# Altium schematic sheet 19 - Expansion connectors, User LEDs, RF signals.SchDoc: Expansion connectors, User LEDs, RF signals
size A3; PageSetup: Record=PageOptions¦CenterHorizontal=True¦CenterVertical=True¦PrintScale=0.70¦XCorrection=1.00¦YCorrection=1.00¦PrintKind=0¦BorderSize=5000000¦LeftOffset=0¦BottomOffset=0¦Orientation=2¦PaperLength=4200¦PaperWidth=2970¦Scale=100¦PaperSource=7¦PrintQuality=600¦MediaType=1¦DitherType=10¦PaperKind=A4¦PrintScaleMode=1; Author: Juan Anzola; SheetNumber: 19; SheetTotal: 21
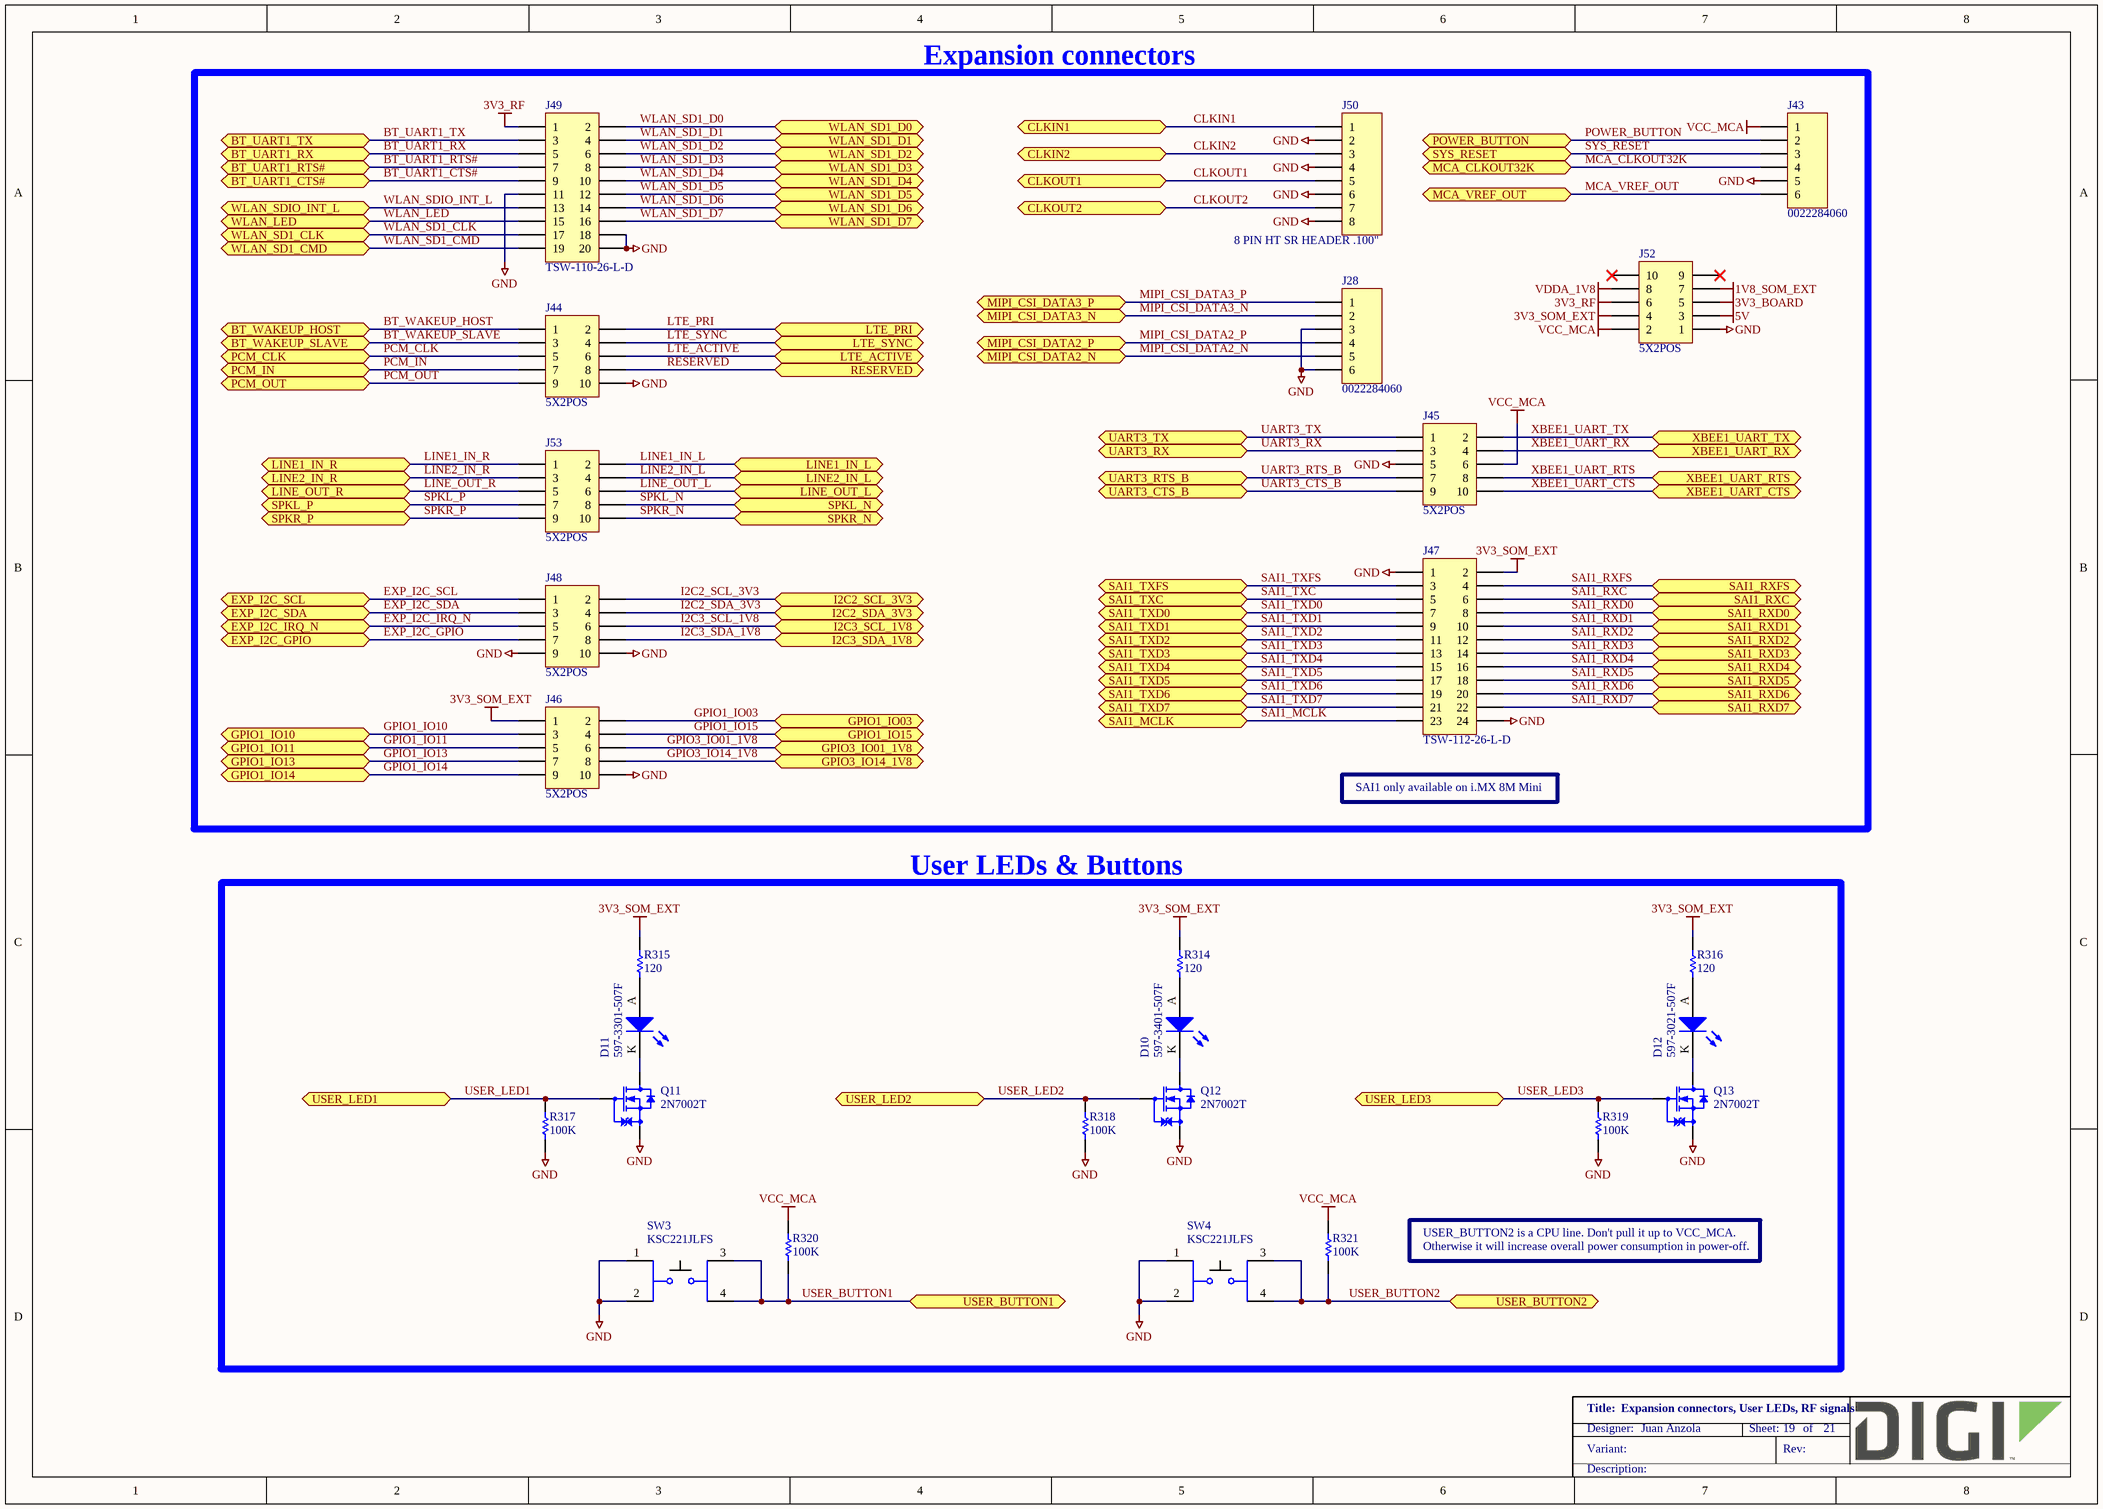
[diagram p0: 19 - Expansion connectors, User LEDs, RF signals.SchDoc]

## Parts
D10  597-3401-507F  [LEDM3020X130N_YELLOW]
D11  597-3301-507F  [LEDM3020X130N_GREEN]
D12  597-3021-507F  [LEDM3020X130N]
J28  0022284060  [MOLEX_0022284060]
J43  0022284060  [MOLEX_0022284060]
J44  5X2POS  [MOLEX_87914-1016]
J45  5X2POS  [MOLEX_87914-1016]
J46  5X2POS  [MOLEX_87914-1016]
J47  TSW-112-26-L-D  [SAMTEC_TSW-112-26-L-D]
J48  5X2POS  [MOLEX_87914-1016]
J49  TSW-110-26-L-D  [SAMTEC_TSW-110-26-L-D]
J50  8 PIN HT SR HEADER .100"  [SAMTEC_TSW-108-07-X-S]
J52  5X2POS  [MOLEX_87914-1016]
J53  5X2POS  [MOLEX_87914-1016]
Q11  2N7002T  [SOTFL50P160X80_GSD-3N]
Q12  2N7002T  [SOTFL50P160X80_GSD-3N]
Q13  2N7002T  [SOTFL50P160X80_GSD-3N]
R314  120  [RESC1005X40N]
R315  120  [RESC1005X40N]
R316  120  [RESC1005X40N]
R317  100K  [RESC1005X40N]
R318  100K  [RESC1005X40N]
R319  100K  [RESC1005X40N]
R320  100K  [RESC1005X40N]
R321  100K  [RESC1005X40N]
SW3  KSC221JLFS  [SW_KSC221J]
SW4  KSC221JLFS  [SW_KSC221J]

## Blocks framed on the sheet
Expansion connectors: J28 J43-J50 J52 J53
User LEDs & Buttons: D10-D12 Q11-Q13 R314-R321 SW3 SW4

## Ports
BT_UART1_CTS# (bidir), BT_UART1_RTS# (bidir), BT_UART1_RX (bidir), BT_UART1_TX (bidir), BT_WAKEUP_HOST (bidir), BT_WAKEUP_SLAVE (bidir), CLKIN1 (bidir), CLKIN2 (bidir), CLKOUT1 (bidir), CLKOUT2 (bidir), EXP_I2C_GPIO (bidir), EXP_I2C_IRQ_N (bidir), EXP_I2C_SCL (bidir), EXP_I2C_SDA (bidir), GPIO1_IO03 (bidir), GPIO1_IO10 (bidir), GPIO1_IO11 (bidir), GPIO1_IO13 (bidir), GPIO1_IO14 (bidir), GPIO1_IO15 (bidir), GPIO3_IO01_1V8 (bidir), GPIO3_IO14_1V8 (bidir), I2C2_SCL_3V3 (bidir), I2C2_SDA_3V3 (bidir), I2C3_SCL_1V8 (bidir), I2C3_SDA_1V8 (bidir), LINE1_IN_L (bidir), LINE1_IN_R (bidir), LINE2_IN_L (bidir), LINE2_IN_R (bidir), LINE_OUT_L (bidir), LINE_OUT_R (bidir), LTE_ACTIVE (bidir), LTE_PRI (bidir), LTE_SYNC (bidir), MCA_CLKOUT32K (bidir), MCA_VREF_OUT (bidir), MIPI_CSI_DATA2_N (bidir), MIPI_CSI_DATA2_P (bidir), MIPI_CSI_DATA3_N (bidir), MIPI_CSI_DATA3_P (bidir), PCM_CLK (bidir), PCM_IN (bidir), PCM_OUT (bidir), POWER_BUTTON (bidir), RESERVED (bidir), SAI1_MCLK (bidir), SAI1_RXC (bidir), SAI1_RXD0 (bidir), SAI1_RXD1 (bidir), SAI1_RXD2 (bidir), SAI1_RXD3 (bidir), SAI1_RXD4 (bidir), SAI1_RXD5 (bidir), SAI1_RXD6 (bidir), SAI1_RXD7 (bidir), SAI1_RXFS (bidir), SAI1_TXC (bidir), SAI1_TXD0 (bidir), SAI1_TXD1 (bidir), SAI1_TXD2 (bidir), SAI1_TXD3 (bidir), SAI1_TXD4 (bidir), SAI1_TXD5 (bidir), SAI1_TXD6 (bidir), SAI1_TXD7 (bidir), SAI1_TXFS (bidir), SPKL_N (bidir), SPKL_P (bidir), SPKR_N (bidir), SPKR_P (bidir), SYS_RESET (bidir), UART3_CTS_B (bidir), UART3_RTS_B (bidir), UART3_RX (bidir), UART3_TX (bidir), USER_BUTTON1 (bidir), USER_BUTTON2 (bidir), USER_LED1 (bidir), USER_LED2 (bidir), USER_LED3 (bidir), WLAN_LED (bidir), WLAN_SD1_CLK (bidir), WLAN_SD1_CMD (bidir), WLAN_SD1_D0 (bidir), WLAN_SD1_D1 (bidir), WLAN_SD1_D2 (bidir), WLAN_SD1_D3 (bidir), WLAN_SD1_D4 (bidir), WLAN_SD1_D5 (bidir), WLAN_SD1_D6 (bidir), WLAN_SD1_D7 (bidir), WLAN_SDIO_INT_L (bidir), XBEE1_UART_CTS (bidir), XBEE1_UART_RTS (bidir), XBEE1_UART_RX (bidir), XBEE1_UART_TX (bidir)

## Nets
1V8_SOM_EXT: J52.7
3V3_BOARD: J52.5
3V3_RF: J49.1 J52.6
3V3_SOM_EXT: J46.1 J47.2 J52.4 R314.2 R315.2 R316.2
5V: J52.3
GND: J28.3 J28.6 J43.5 J44.10 J45.5 J46.10 J47.1 J47.24 J48.9 J48.10 J49.11 J49.18 J49.20 J50.2 J50.4 J50.6 J50.8 J52.1 Q11.S Q12.S Q13.S R317.2 R318.2 R319.2 SW3.1 SW3.2 SW4.1 SW4.2
VCC_MCA: J43.1 J45.6 J52.2 R320.2 R321.2
VDDA_1V8: J52.8
BT_UART1_CTS#: J49.9 ; port BT_UART1_CTS#
BT_UART1_RTS#: J49.7 ; port BT_UART1_RTS#
BT_UART1_RX: J49.5 ; port BT_UART1_RX
BT_UART1_TX: J49.3 ; port BT_UART1_TX
BT_WAKEUP_HOST: J44.1 ; port BT_WAKEUP_HOST
BT_WAKEUP_SLAVE: J44.3 ; port BT_WAKEUP_SLAVE
CLKIN1: J50.1 ; port CLKIN1
CLKIN2: J50.3 ; port CLKIN2
CLKOUT1: J50.5 ; port CLKOUT1
CLKOUT2: J50.7 ; port CLKOUT2
EXP_I2C_GPIO: J48.7 ; port EXP_I2C_GPIO
EXP_I2C_IRQ_N: J48.5 ; port EXP_I2C_IRQ_N
EXP_I2C_SCL: J48.1 ; port EXP_I2C_SCL
EXP_I2C_SDA: J48.3 ; port EXP_I2C_SDA
GPIO1_IO03: J46.2 ; port GPIO1_IO03
GPIO1_IO10: J46.3 ; port GPIO1_IO10
GPIO1_IO11: J46.5 ; port GPIO1_IO11
GPIO1_IO13: J46.7 ; port GPIO1_IO13
GPIO1_IO14: J46.9 ; port GPIO1_IO14
GPIO1_IO15: J46.4 ; port GPIO1_IO15
GPIO3_IO01_1V8: J46.6 ; port GPIO3_IO01_1V8
GPIO3_IO14_1V8: J46.8 ; port GPIO3_IO14_1V8
I2C2_SCL_3V3: J48.2 ; port I2C2_SCL_3V3
I2C2_SDA_3V3: J48.4 ; port I2C2_SDA_3V3
I2C3_SCL_1V8: J48.6 ; port I2C3_SCL_1V8
I2C3_SDA_1V8: J48.8 ; port I2C3_SDA_1V8
LINE1_IN_L: J53.2 ; port LINE1_IN_L
LINE1_IN_R: J53.1 ; port LINE1_IN_R
LINE2_IN_L: J53.4 ; port LINE2_IN_L
LINE2_IN_R: J53.3 ; port LINE2_IN_R
LINE_OUT_L: J53.6 ; port LINE_OUT_L
LINE_OUT_R: J53.5 ; port LINE_OUT_R
LTE_ACTIVE: J44.6 ; port LTE_ACTIVE
LTE_PRI: J44.2 ; port LTE_PRI
LTE_SYNC: J44.4 ; port LTE_SYNC
MCA_CLKOUT32K: J43.4 ; port MCA_CLKOUT32K
MCA_VREF_OUT: J43.6 ; port MCA_VREF_OUT
MIPI_CSI_DATA2_N: J28.5 ; port MIPI_CSI_DATA2_N
MIPI_CSI_DATA2_P: J28.4 ; port MIPI_CSI_DATA2_P
MIPI_CSI_DATA3_N: J28.2 ; port MIPI_CSI_DATA3_N
MIPI_CSI_DATA3_P: J28.1 ; port MIPI_CSI_DATA3_P
PCM_CLK: J44.5 ; port PCM_CLK
PCM_IN: J44.7 ; port PCM_IN
PCM_OUT: J44.9 ; port PCM_OUT
POWER_BUTTON: J43.2 ; port POWER_BUTTON
RESERVED: J44.8 ; port RESERVED
SAI1_MCLK: J47.23 ; port SAI1_MCLK
SAI1_RXC: J47.6 ; port SAI1_RXC
SAI1_RXD0: J47.8 ; port SAI1_RXD0
SAI1_RXD1: J47.10 ; port SAI1_RXD1
SAI1_RXD2: J47.12 ; port SAI1_RXD2
SAI1_RXD3: J47.14 ; port SAI1_RXD3
SAI1_RXD4: J47.16 ; port SAI1_RXD4
SAI1_RXD5: J47.18 ; port SAI1_RXD5
SAI1_RXD6: J47.20 ; port SAI1_RXD6
SAI1_RXD7: J47.22 ; port SAI1_RXD7
SAI1_RXFS: J47.4 ; port SAI1_RXFS
SAI1_TXC: J47.5 ; port SAI1_TXC
SAI1_TXD0: J47.7 ; port SAI1_TXD0
SAI1_TXD1: J47.9 ; port SAI1_TXD1
SAI1_TXD2: J47.11 ; port SAI1_TXD2
SAI1_TXD3: J47.13 ; port SAI1_TXD3
SAI1_TXD4: J47.15 ; port SAI1_TXD4
SAI1_TXD5: J47.17 ; port SAI1_TXD5
SAI1_TXD6: J47.19 ; port SAI1_TXD6
SAI1_TXD7: J47.21 ; port SAI1_TXD7
SAI1_TXFS: J47.3 ; port SAI1_TXFS
SPKL_N: J53.8 ; port SPKL_N
SPKL_P: J53.7 ; port SPKL_P
SPKR_N: J53.10 ; port SPKR_N
SPKR_P: J53.9 ; port SPKR_P
SYS_RESET: J43.3 ; port SYS_RESET
UART3_CTS_B: J45.9 ; port UART3_CTS_B
UART3_RTS_B: J45.7 ; port UART3_RTS_B
UART3_RX: J45.3 ; port UART3_RX
UART3_TX: J45.1 ; port UART3_TX
USER_BUTTON1: R320.1 SW3.3 SW3.4 ; port USER_BUTTON1
USER_BUTTON2: R321.1 SW4.3 SW4.4 ; port USER_BUTTON2
USER_LED1: Q11.G R317.1 ; port USER_LED1
USER_LED2: Q12.G R318.1 ; port USER_LED2
USER_LED3: Q13.G R319.1 ; port USER_LED3
WLAN_LED: J49.15 ; port WLAN_LED
WLAN_SD1_CLK: J49.17 ; port WLAN_SD1_CLK
WLAN_SD1_CMD: J49.19 ; port WLAN_SD1_CMD
WLAN_SD1_D0: J49.2 ; port WLAN_SD1_D0
WLAN_SD1_D1: J49.4 ; port WLAN_SD1_D1
WLAN_SD1_D2: J49.6 ; port WLAN_SD1_D2
WLAN_SD1_D3: J49.8 ; port WLAN_SD1_D3
WLAN_SD1_D4: J49.10 ; port WLAN_SD1_D4
WLAN_SD1_D5: J49.12 ; port WLAN_SD1_D5
WLAN_SD1_D6: J49.14 ; port WLAN_SD1_D6
WLAN_SD1_D7: J49.16 ; port WLAN_SD1_D7
WLAN_SDIO_INT_L: J49.13 ; port WLAN_SDIO_INT_L
XBEE1_UART_CTS: J45.10 ; port XBEE1_UART_CTS
XBEE1_UART_RTS: J45.8 ; port XBEE1_UART_RTS
XBEE1_UART_RX: J45.4 ; port XBEE1_UART_RX
XBEE1_UART_TX: J45.2 ; port XBEE1_UART_TX
NetD10_A: D10.A R314.1
NetD10_K: D10.K Q12.D
NetD11_A: D11.A R315.1
NetD11_K: D11.K Q11.D
NetD12_A: D12.A R316.1
NetD12_K: D12.K Q13.D

Not connected (* = marked no-connect by the designer): J52 9* 10*

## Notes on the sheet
- SAI1 only available on i.MX 8M Mini
- USER_BUTTON2 is a CPU line. Don't pull it up to VCC_MCA.
- Otherwise it will increase overall power consumption in power-off.

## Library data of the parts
D10 = 1001188: LED YELLOW 588NM 1208 SMD; Manufacturer: Dialight; Note: 17050842 = Digi No. for GE WDNU; Digi_PN: 17050387; Component_Life_Cycle_State: Reviewed; Area: 6
D11 = 1001189: LED GREEN 573NM 1208 SMD; Manufacturer: Dialight; Note: 17050846 = Digi PN for GE WDNU II; Digi_PN: 17050183; Component_Life_Cycle_State: Reviewed; Area: 6
D12 = 1001190: LED RED 653NM 20MA 1208 SMD; Manufacturer: Dialight; Digi_PN: 17050184; Component_Life_Cycle_State: Reviewed; Area: 6
J28 J43 = 1002721: CONN HEADER VERT 6POS 2.54MM; Part_Type: Connector; Manufacturer: Molex; Digi_PN: 0790004; Component_Life_Cycle_State: Reviewed; Area: 42,49
J44-J46 J48 J52 J53 = 1001335: CONN HEADER 10POS DL VERT T/H; Part_Type: Connector; Manufacturer: Molex; Manufacturer_Part_Number: 87914-1016; Note: Check symbol pin-out upon reactivation; Digi_PN: 18000793; Component_Life_Cycle_State: Abandoned; Area: 63,5
J47 = 1002752: CONN HEADER VERT 24POS 2.54MM; Part_Type: Connector; Manufacturer: Samtec; Digi_PN: 18000795; Component_Life_Cycle_State: Created; Area: 179,25
J49 = 1002751: CONN HEADER VERT 20POS 2.54MM; Part_Type: Connector; Manufacturer: Samtec; Digi_PN: 01730020; Component_Life_Cycle_State: Created; Area: 150,08
J50 = 1000191: CONN HEADER 8POS .100" SNGL; Part_Type: Connector; Manufacturer: Samtec; Manufacturer_Part_Number: TSW-108-07-G-S; Component_Life_Cycle_State: Reviewed; Area: 51,61; Digi_PN: 18000792
Q11-Q13 = 1000715: MOSFET N-CH 60V 115MA SOT-523F; Part_Type: Transistor; Manufacturer: Fairchild Semiconductor; Digi_PN: 17050797; Component_Life_Cycle_State: CAD Reviewed; Area: 3.06; Project: SmartMeter2; Note: 17050841 = Digi No. for GE WDNU
R314-R316 = 1001158: RES 120 OHM 1/16W 1% 0402 SMD; Part_Type: Resistor; Manufacturer: Yageo; Manufacturer_Part_Number: RC0402FR-07120RL; Note: 13051102 = Digi No. for GE WDNU; Digi_PN: 13050832; Component_Life_Cycle_State: Reviewed; Area: 0,95; Project: CCWMX6_SBC board
R317-R319 = 1000480: RES 100K OHM 1/10W 1% 0402 SMD; Part_Type: Resistor; Manufacturer: Panasonic - ECG; Manufacturer_Part_Number: ERJ-2RKF1003X; Digi_PN: 13051063; Component_Life_Cycle_State: CAD Reviewed; Area: 0.95; Project: KITT; Power_WV_SRF: 100
R320 R321 = 1000480: RES 100K OHM 1/10W 1% 0402 SMD; Part_Type: Resistor; Manufacturer: Panasonic - ECG; Manufacturer_Part_Number: ERJ-2RKF1003X; Digi_PN: 13051063; Component_Life_Cycle_State: CAD Reviewed; Area: 0,95; Project: KITT; Power_WV_SRF: 100
SW3 SW4 = 1001124: SWITCH TACTILE SPST-NO 0.05A 32V; Manufacturer: ITT; Digi_PN: 22000059; Component_Life_Cycle_State: Reviewed; Area: 37; Project: CCWMX6_SBC board; Note: 22000295 = Digi No. for GE WDNU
